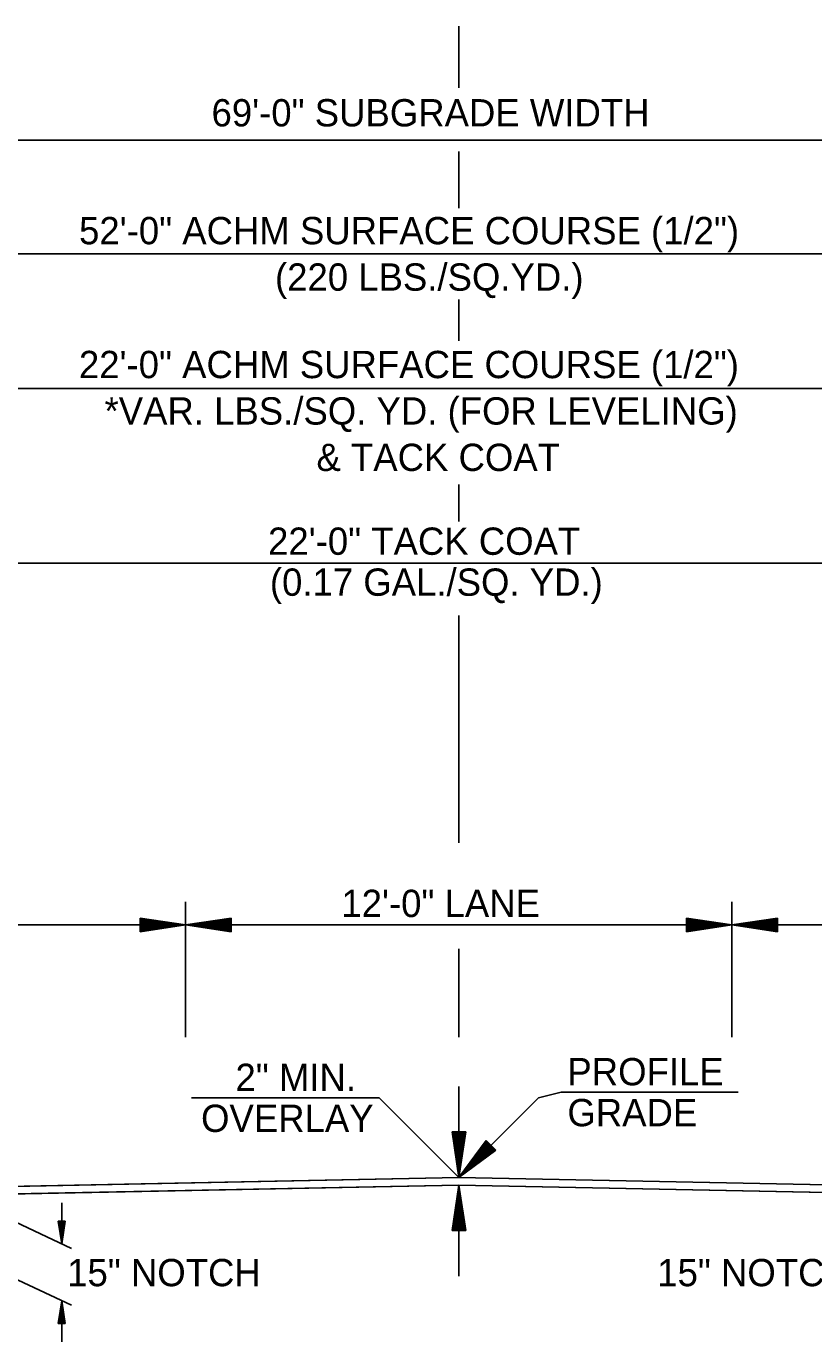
# Model space of a CAD drawing. Extents: x 1371763 to 1372860, y 385599 to 385872.
# Drawn here: x 1372073.89 to 1372091.19, y 385644.87 to 385673.78 of the extents above; entities that cross this region are included whole.
import ezdxf

# ---------------------------------------------------------------- set-up
doc = ezdxf.new("R2010")
doc.units = 0
doc.layers.add('R_Draft', color=7, linetype='Continuous')

msp = doc.modelspace()

# ---------------------------------------------------------------- linework, layer by layer
at = {"layer": 'R_Draft'}
for p, q in [((1372083.393, 385672.427), (1372083.393, 385673.777)), ((1372048.826, 385671.277), (1372117.962, 385671.277)), ((1372083.393, 385669.777), (1372083.393, 385671.027)), ((1372057.39, 385668.777), (1372109.391, 385668.777)), ((1372083.393, 385666.868), (1372083.393, 385667.777)), ((1372072.393, 385665.821), (1372094.393, 385665.821)), ((1372083.39, 385662.896), (1372083.39, 385663.707)), ((1372072.393, 385661.977), (1372094.393, 385661.977)), ((1372083.391, 385655.836), (1372083.39, 385660.832)), ((1372077.39, 385651.566), (1372077.39, 385654.539)), ((1372089.39, 385651.566), (1372089.39, 385654.539)), ((1372076.39, 385654.182), (1372077.39, 385654.032)), ((1372076.39, 385653.882), (1372076.39, 385654.182)), ((1372076.39, 385654.157), (1372077.223, 385654.032)), ((1372076.39, 385654.132), (1372077.051, 385654.032)), ((1372078.39, 385654.182), (1372077.39, 385654.032)), ((1372078.39, 385654.157), (1372077.557, 385654.032)), ((1372078.39, 385654.132), (1372077.729, 385654.032)), ((1372078.39, 385653.882), (1372078.39, 385654.182)), ((1372088.39, 385654.182), (1372089.39, 385654.032)), ((1372088.39, 385653.882), (1372088.39, 385654.182)), ((1372088.39, 385654.157), (1372089.223, 385654.032)), ((1372088.39, 385654.132), (1372089.051, 385654.032)), ((1372090.39, 385654.182), (1372089.39, 385654.032)), ((1372090.39, 385654.157), (1372089.557, 385654.032)), ((1372090.39, 385654.132), (1372089.729, 385654.032)), ((1372090.39, 385653.882), (1372090.39, 385654.182)), ((1372065.39, 385654.032), (1372077.39, 385654.032)), ((1372076.39, 385654.107), (1372076.885, 385654.032)), ((1372076.39, 385654.081), (1372076.715, 385654.032)), ((1372076.39, 385654.056), (1372076.548, 385654.032)), ((1372076.39, 385653.882), (1372077.39, 385654.032)), ((1372076.39, 385653.984), (1372076.715, 385654.032)), ((1372076.39, 385653.933), (1372077.051, 385654.032)), ((1372076.39, 385653.907), (1372077.223, 385654.032)), ((1372076.39, 385653.958), (1372076.885, 385654.032)), ((1372076.39, 385654.009), (1372076.548, 385654.032)), ((1372078.39, 385653.882), (1372077.39, 385654.032)), ((1372077.39, 385654.032), (1372089.39, 385654.032)), ((1372078.39, 385653.907), (1372077.557, 385654.032)), ((1372078.39, 385653.933), (1372077.729, 385654.032)), ((1372078.39, 385654.107), (1372077.896, 385654.032)), ((1372078.39, 385653.958), (1372077.896, 385654.032)), ((1372078.39, 385654.081), (1372078.065, 385654.032)), ((1372078.39, 385653.984), (1372078.065, 385654.032)), ((1372078.39, 385654.056), (1372078.232, 385654.032)), ((1372078.39, 385654.009), (1372078.232, 385654.032)), ((1372088.39, 385654.107), (1372088.885, 385654.032)), ((1372088.39, 385654.081), (1372088.715, 385654.032)), ((1372088.39, 385654.056), (1372088.548, 385654.032)), ((1372088.39, 385653.882), (1372089.39, 385654.032)), ((1372088.39, 385653.984), (1372088.715, 385654.032)), ((1372088.39, 385653.933), (1372089.051, 385654.032)), ((1372088.39, 385653.907), (1372089.223, 385654.032)), ((1372088.39, 385653.958), (1372088.885, 385654.032)), ((1372088.39, 385654.009), (1372088.548, 385654.032)), ((1372089.39, 385654.032), (1372101.39, 385654.032)), ((1372090.39, 385653.882), (1372089.39, 385654.032)), ((1372090.39, 385653.907), (1372089.557, 385654.032)), ((1372090.39, 385653.933), (1372089.729, 385654.032)), ((1372090.39, 385654.107), (1372089.896, 385654.032)), ((1372090.39, 385653.958), (1372089.896, 385654.032)), ((1372090.39, 385654.081), (1372090.065, 385654.032)), ((1372090.39, 385653.984), (1372090.065, 385654.032)), ((1372090.39, 385654.056), (1372090.232, 385654.032)), ((1372090.39, 385654.009), (1372090.232, 385654.032)), ((1372083.391, 385651.561), (1372083.391, 385653.502)), ((1372083.393, 385648.481), (1372083.393, 385650.481)), ((1372085.143, 385650.231), (1372085.643, 385650.356)), ((1372085.643, 385650.356), (1372089.529, 385650.356)), ((1372081.643, 385650.231), (1372077.517, 385650.231)), ((1372083.393, 385648.481), (1372081.643, 385650.231)), ((1372083.393, 385648.481), (1372085.143, 385650.231)), ((1372083.243, 385649.481), (1372083.393, 385648.481)), ((1372083.243, 385649.481), (1372083.543, 385649.481)), ((1372083.268, 385649.481), (1372083.393, 385648.648)), ((1372083.294, 385649.481), (1372083.393, 385648.82)), ((1372083.319, 385649.481), (1372083.393, 385648.986)), ((1372083.345, 385649.481), (1372083.393, 385649.156)), ((1372083.37, 385649.481), (1372083.393, 385649.323)), ((1372083.543, 385649.481), (1372083.393, 385648.481)), ((1372083.442, 385649.481), (1372083.393, 385649.156)), ((1372083.493, 385649.481), (1372083.393, 385648.82)), ((1372083.518, 385649.481), (1372083.393, 385648.648)), ((1372083.468, 385649.481), (1372083.393, 385648.986)), ((1372083.417, 385649.481), (1372083.393, 385649.323)), ((1372083.994, 385649.294), (1372083.393, 385648.481)), ((1372084.012, 385649.276), (1372083.511, 385648.599)), ((1372084.03, 385649.258), (1372083.633, 385648.72)), ((1372084.048, 385649.24), (1372083.751, 385648.838)), ((1372084.066, 385649.222), (1372083.871, 385648.958)), ((1372084.084, 385649.204), (1372083.989, 385649.076)), ((1372084.206, 385649.082), (1372083.994, 385649.294)), ((1372084.206, 385649.082), (1372083.393, 385648.481)), ((1372084.189, 385649.099), (1372083.511, 385648.599)), ((1372084.171, 385649.117), (1372083.633, 385648.72)), ((1372084.153, 385649.135), (1372083.751, 385648.838)), ((1372084.135, 385649.154), (1372083.871, 385648.958)), ((1372084.117, 385649.171), (1372083.989, 385649.076)), ((1372083.393, 385648.481), (1372065.393, 385648.121)), ((1372083.393, 385648.481), (1372101.393, 385648.121)), ((1372083.393, 385648.314), (1372065.309, 385647.952)), ((1372072.394, 385648.094), (1372074.881, 385646.922)), ((1372083.243, 385647.314), (1372083.393, 385648.314)), ((1372083.268, 385647.314), (1372083.393, 385648.147)), ((1372083.393, 385648.314), (1372101.477, 385647.952)), ((1372083.543, 385647.314), (1372083.393, 385648.314)), ((1372083.393, 385648.314), (1372083.393, 385646.314)), ((1372083.518, 385647.314), (1372083.393, 385648.147)), ((1372074.669, 385647.022), (1372074.669, 385647.922)), ((1372083.294, 385647.314), (1372083.393, 385647.975)), ((1372083.319, 385647.314), (1372083.393, 385647.809)), ((1372083.493, 385647.314), (1372083.393, 385647.975)), ((1372083.468, 385647.314), (1372083.393, 385647.809)), ((1372074.594, 385647.522), (1372074.669, 385647.022)), ((1372074.594, 385647.522), (1372074.744, 385647.522)), ((1372074.606, 385647.522), (1372074.669, 385647.106)), ((1372074.619, 385647.522), (1372074.669, 385647.192)), ((1372074.631, 385647.522), (1372074.669, 385647.275)), ((1372074.644, 385647.522), (1372074.669, 385647.36)), ((1372074.657, 385647.522), (1372074.669, 385647.443)), ((1372074.744, 385647.522), (1372074.669, 385647.022)), ((1372074.693, 385647.522), (1372074.669, 385647.36)), ((1372074.718, 385647.522), (1372074.669, 385647.192)), ((1372074.731, 385647.522), (1372074.669, 385647.106)), ((1372074.706, 385647.522), (1372074.669, 385647.275)), ((1372074.68, 385647.522), (1372074.669, 385647.443)), ((1372083.344, 385647.314), (1372083.393, 385647.639)), ((1372083.37, 385647.314), (1372083.393, 385647.472)), ((1372083.442, 385647.314), (1372083.393, 385647.639)), ((1372083.417, 385647.314), (1372083.393, 385647.472)), ((1372083.543, 385647.314), (1372083.243, 385647.314)), ((1372072.393, 385646.844), (1372074.881, 385645.672)), ((1372074.593, 385645.272), (1372074.668, 385645.772)), ((1372074.743, 385645.272), (1372074.668, 385645.772)), ((1372074.668, 385644.872), (1372074.668, 385645.772)), ((1372074.606, 385645.272), (1372074.668, 385645.689)), ((1372074.619, 385645.272), (1372074.668, 385645.603)), ((1372074.631, 385645.272), (1372074.668, 385645.519)), ((1372074.731, 385645.272), (1372074.668, 385645.689)), ((1372074.718, 385645.272), (1372074.668, 385645.603)), ((1372074.706, 385645.272), (1372074.668, 385645.519)), ((1372074.743, 385645.272), (1372074.593, 385645.272)), ((1372074.644, 385645.272), (1372074.668, 385645.435)), ((1372074.657, 385645.272), (1372074.668, 385645.351)), ((1372074.693, 385645.272), (1372074.668, 385645.435)), ((1372074.68, 385645.272), (1372074.668, 385645.351))]:
    msp.add_line(p, q, dxfattribs=at)
msp.add_lwpolyline([(1372083.393, 385648.481), (1372065.393, 385648.121), (1372057.393, 385647.801), (1372057.393, 385647.636), (1372065.309, 385647.952), (1372072.394, 385648.094), (1372083.393, 385648.314), (1372094.392, 385648.094), (1372101.477, 385647.952), (1372109.393, 385647.636), (1372109.393, 385647.801), (1372101.393, 385648.121)], close=True, dxfattribs=at)

# ---------------------------------------------------------------- texts
for s, p in [('69\'-0" SUBGRADE WIDTH', (1372077.96, 385671.577)), ('52\'-0" ACHM SURFACE COURSE (1/2")', (1372075.05, 385668.987)), ('(220 LBS./SQ.YD.)', (1372079.354, 385667.967)), ('22\'-0" ACHM SURFACE COURSE (1/2")', (1372075.047, 385666.045)), ('*VAR. LBS./SQ. YD. (FOR LEVELING)', (1372075.609, 385665.025)), ('& TACK COAT', (1372080.265, 385664.005)), ('22\'-0" TACK COAT', (1372079.202, 385662.163)), ('(0.17 GAL./SQ. YD.)', (1372079.242, 385661.263)), ('12\'-0" LANE', (1372080.812, 385654.204))]:
    msp.add_text(s, height=0.6, rotation=360, dxfattribs=at).set_placement(p)
for s, p in [('2" MIN.', (1372078.486, 385650.381)), ('PROFILE', (1372085.777, 385650.506)), ('OVERLAY', (1372077.73, 385649.481)), ('GRADE', (1372085.777, 385649.606)), ('15" NOTCH', (1372074.789, 385646.091)), ('15" NOTCH', (1372087.751, 385646.091))]:
    msp.add_text(s, height=0.6, dxfattribs=at).set_placement(p)

doc.saveas('drawing.dxf')
